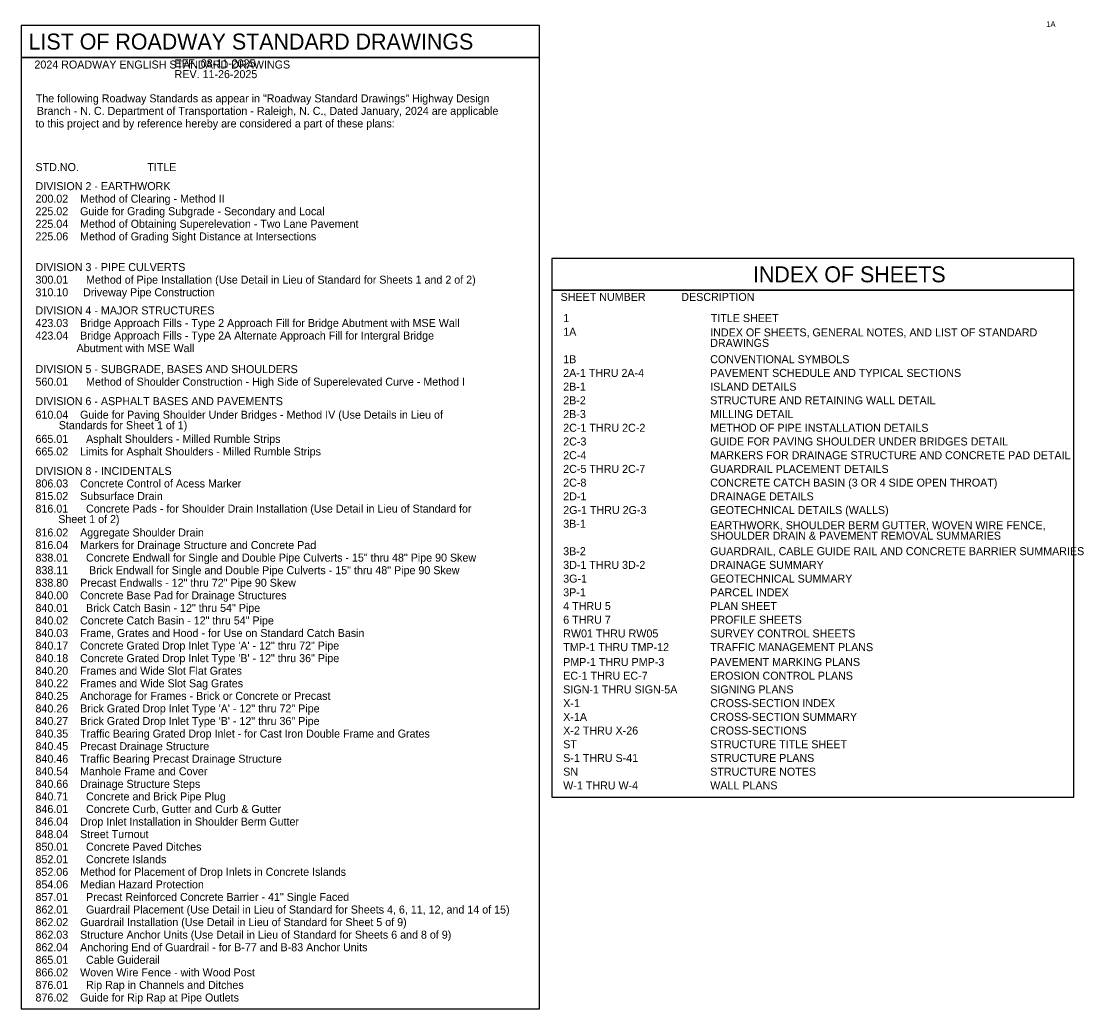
# Model space of a CAD drawing. Extents: x 4758945 to 4761296, y 1218805 to 1219686.
# Drawn here: x 4760367 to 4761296, y 1218805 to 1219669 of the extents above; entities that cross this region are included whole.
import ezdxf

# ---------------------------------------------------------------- set-up
doc = ezdxf.new("R2010")
doc.units = 0
for name, color, linetype in [('Old_Level_44', 7, 'Continuous'), ('Scratch_Level_3', 7, 'Continuous'), ('Typical Text Grade Point CELL', 7, 'Continuous')]:
    doc.layers.add(name, color=color, linetype=linetype)

msp = doc.modelspace()

# ---------------------------------------------------------------- linework, layer by layer
at = {"layer": 'Old_Level_44'}
msp.add_line((4760830.64, 1219433.79), (4761287.5, 1219433.79), dxfattribs=at)
msp.add_lwpolyline([(4760366.66, 1219637.5), (4760820.07, 1219637.5), (4760820.07, 1219665.5), (4760366.66, 1219665.5)], close=True, dxfattribs=at)
at = {"layer": 'Typical Text Grade Point CELL'}
for points in [[(4760366.66, 1218805), (4760820.07, 1218805), (4760820.07, 1219637.5), (4760366.66, 1219637.5)], [(4760830.64, 1219433.79), (4761287.5, 1219433.79), (4761287.5, 1219461.64), (4760830.64, 1219461.64)], [(4760830.64, 1218990.15), (4761287.5, 1218990.15), (4761287.5, 1219433.79), (4760830.64, 1219433.79)]]:
    msp.add_lwpolyline(points, close=True, dxfattribs=at)

# ---------------------------------------------------------------- texts
at = {"layer": 'Old_Level_44'}
for s, p in [('LIST OF ROADWAY STANDARD DRAWINGS', (4760373.07, 1219644.5)), ('INDEX OF SHEETS', (4761006.75, 1219440.79))]:
    msp.add_text(s, height=14, dxfattribs=at).set_placement(p)
at = {"layer": 'Scratch_Level_3'}
msp.add_text('1A', height=5, dxfattribs=at).set_placement((4761263.23, 1219664.27))
at = {"layer": 'Typical Text Grade Point CELL'}
for s, p in [('2024 ROADWAY ENGLISH STANDARD DRAWINGS', (4760378.18, 1219627.88)), ('                                                      EFF. 08-11-2025', (4760360.38, 1219628.9)), ('                                                      EFF. 08-11-2025', (4760360.38, 1219628.9)), ('                                                      REV. 11-26-2025', (4760360.38, 1219619.46)), ('The following Roadway Standards as appear in "Roadway Standard Drawings" Highway Design ', (4760379.35, 1219598.31)), ('Branch - N. C. Department of Transportation - Raleigh, N. C., Dated January, 2024 are applicable ', (4760380.29, 1219587.31)), ('to this project and by reference hereby are considered a part of these plans:', (4760379.12, 1219576.31)), ('STD.NO.                       TITLE', (4760379.12, 1219538.13)), ('DIVISION 2 - EARTHWORK', (4760379.12, 1219521.48)), ('200.02    Method of Clearing - Method II', (4760379.12, 1219510.48)), ('225.02    Guide for Grading Subgrade - Secondary and Local', (4760379.12, 1219499.48)), ('225.04    Method of Obtaining Superelevation - Two Lane Pavement', (4760379.12, 1219488.48)), ('225.06    Method of Grading Sight Distance at Intersections', (4760379.12, 1219477.48)), ('DIVISION 3 - PIPE CULVERTS', (4760379.12, 1219450.59)), ('300.01      Method of Pipe Installation (Use Detail in Lieu of Standard for Sheets 1 and 2 of 2)', (4760379.12, 1219439.59)), ('310.10     Driveway Pipe Construction', (4760379.12, 1219428.59)), ('SHEET NUMBER            DESCRIPTION', (4760838.46, 1219424.5)), ('DIVISION 4 - MAJOR STRUCTURES', (4760379.12, 1219412.69)), ('1 ', (4760840.74, 1219405.98)), ('TITLE SHEET', (4760969.86, 1219405.98)), ('423.03    Bridge Approach Fills - Type 2 Approach Fill for Bridge Abutment with MSE Wall', (4760379.12, 1219401.69)), ('423.04    Bridge Approach Fills - Type 2A Alternate Approach Fill for Intergral Bridge', (4760379.12, 1219390.69)), ('1A ', (4760840.74, 1219393.98)), ('INDEX OF SHEETS, GENERAL NOTES, AND LIST OF STANDARD ', (4760969.34, 1219393.44)), ('    Abutment with MSE Wall', (4760404.66, 1219379.69)), ('DRAWINGS', (4760969.34, 1219384.26)), ('1B  ', (4760840.74, 1219369.98)), ('CONVENTIONAL SYMBOLS ', (4760969.34, 1219369.98)), ('DIVISION 5 - SUBGRADE, BASES AND SHOULDERS', (4760379.12, 1219361.3)), ('560.01      Method of Shoulder Construction - High Side of Superelevated Curve - Method I', (4760379.12, 1219350.3)), ('2A-1 THRU 2A-4', (4760840.74, 1219357.98)), ('PAVEMENT SCHEDULE AND TYPICAL SECTIONS', (4760969.34, 1219357.98)), ('2B-1   ', (4760840.74, 1219345.98)), ('ISLAND DETAILS', (4760969.34, 1219345.98)), ('DIVISION 6 - ASPHALT BASES AND PAVEMENTS', (4760379.12, 1219333.27)), ('2B-2', (4760840.74, 1219333.98)), ('STRUCTURE AND RETAINING WALL DETAIL', (4760969.34, 1219333.98)), ('610.04    Guide for Paving Shoulder Under Bridges - Method IV (Use Details in Lieu of ', (4760379.12, 1219321.42)), ('2B-3', (4760840.74, 1219321.98)), ('MILLING DETAIL', (4760969.34, 1219321.98)), ('       Standards for Sheet 1 of 1)', (4760381.27, 1219312.24)), ('2C-1 THRU 2C-2  ', (4760840.74, 1219309.98)), ('METHOD OF PIPE INSTALLATION DETAILS', (4760969.34, 1219309.98)), ('665.01      Asphalt Shoulders - Milled Rumble Strips', (4760379.12, 1219300.27)), ('2C-3 ', (4760840.74, 1219297.98)), ('GUIDE FOR PAVING SHOULDER UNDER BRIDGES DETAIL', (4760969.34, 1219297.98)), ('665.02    Limits for Asphalt Shoulders - Milled Rumble Strips', (4760379.12, 1219289.27)), ('2C-4', (4760840.74, 1219285.98)), ('MARKERS FOR DRAINAGE STRUCTURE AND CONCRETE PAD DETAIL', (4760969.34, 1219285.98)), ('DIVISION 8 - INCIDENTALS', (4760379.12, 1219272.23)), ('2C-5 THRU 2C-7   ', (4760840.74, 1219273.98)), ('GUARDRAIL PLACEMENT DETAILS', (4760969.34, 1219273.98)), ('806.03    Concrete Control of Acess Marker', (4760379.12, 1219261.23)), ('2C-8 ', (4760840.74, 1219261.98)), ('CONCRETE CATCH BASIN (3 OR 4 SIDE OPEN THROAT)', (4760969.34, 1219261.98)), ('815.02    Subsurface Drain', (4760379.12, 1219250.23)), ('2D-1  ', (4760840.74, 1219249.98)), ('DRAINAGE DETAILS', (4760969.34, 1219249.98)), ('816.01      Concrete Pads - for Shoulder Drain Installation (Use Detail in Lieu of Standard for ', (4760379.12, 1219239.23)), ('       Sheet 1 of 2)', (4760380.81, 1219230.05)), ('2G-1 THRU 2G-3 ', (4760840.74, 1219237.98)), ('GEOTECHNICAL DETAILS (WALLS)', (4760969.34, 1219237.98)), ('3B-1     ', (4760840.74, 1219225.98)), ('EARTHWORK, SHOULDER BERM GUTTER, WOVEN WIRE FENCE, ', (4760969.34, 1219224.7)), ('816.02    Aggregate Shoulder Drain', (4760379.12, 1219218.34)), ('SHOULDER DRAIN & PAVEMENT REMOVAL SUMMARIES', (4760969.34, 1219215.52)), ('816.04    Markers for Drainage Structure and Concrete Pad', (4760379.12, 1219207.34)), ('3B-2     ', (4760840.74, 1219201.98)), ('GUARDRAIL, CABLE GUIDE RAIL AND CONCRETE BARRIER SUMMARIES', (4760969.34, 1219201.98)), ('838.01      Concrete Endwall for Single and Double Pipe Culverts - 15" thru 48" Pipe 90 Skew', (4760379.12, 1219196.34)), ('838.11       Brick Endwall for Single and Double Pipe Culverts - 15" thru 48" Pipe 90 Skew', (4760379.12, 1219185.34)), ('3D-1 THRU 3D-2     ', (4760840.74, 1219189.98)), ('DRAINAGE SUMMARY', (4760969.34, 1219189.98)), ('838.80    Precast Endwalls - 12" thru 72" Pipe 90 Skew', (4760379.12, 1219174.34)), ('3G-1     ', (4760840.74, 1219177.98)), ('GEOTECHNICAL SUMMARY', (4760969.34, 1219177.98)), ('3P-1     ', (4760840.74, 1219165.98)), ('PARCEL INDEX', (4760969.34, 1219165.98)), ('840.00    Concrete Base Pad for Drainage Structures', (4760379.12, 1219163.34)), ('840.01      Brick Catch Basin - 12" thru 54" Pipe', (4760379.12, 1219152.34)), ('4 THRU 5  ', (4760840.74, 1219153.98)), ('PLAN SHEET', (4760969.34, 1219153.98)), ('840.02    Concrete Catch Basin - 12" thru 54" Pipe', (4760379.12, 1219141.34)), ('6 THRU 7', (4760840.74, 1219141.98)), ('PROFILE SHEETS', (4760969.34, 1219141.98)), ('840.03    Frame, Grates and Hood - for Use on Standard Catch Basin', (4760379.12, 1219130.34)), ('RW01 THRU RW05', (4760840.74, 1219129.98)), ('SURVEY CONTROL SHEETS', (4760969.34, 1219129.98)), ('840.17    Concrete Grated Drop Inlet Type \'A\' - 12" thru 72" Pipe', (4760379.12, 1219119.34)), ('TMP-1 THRU TMP-12', (4760840.74, 1219117.98)), ('TRAFFIC MANAGEMENT PLANS', (4760969.34, 1219117.98)), ('840.18    Concrete Grated Drop Inlet Type \'B\' - 12" thru 36" Pipe', (4760379.12, 1219108.34)), ('PMP-1 THRU PMP-3', (4760840.74, 1219104.98)), ('PAVEMENT MARKING PLANS', (4760969.34, 1219104.98)), ('840.20    Frames and Wide Slot Flat Grates', (4760379.12, 1219097.34)), ('EC-1 THRU EC-7', (4760840.74, 1219092.98)), ('EROSION CONTROL PLANS', (4760969.34, 1219092.98)), ('840.22    Frames and Wide Slot Sag Grates', (4760379.12, 1219086.34)), ('SIGN-1 THRU SIGN-5A', (4760840.74, 1219080.98)), ('SIGNING PLANS', (4760969.34, 1219080.98)), ('840.25    Anchorage for Frames - Brick or Concrete or Precast', (4760379.12, 1219075.34)), ('840.26    Brick Grated Drop Inlet Type \'A\' - 12" thru 72" Pipe', (4760379.12, 1219064.34)), ('X-1', (4760840.74, 1219068.98)), ('CROSS-SECTION INDEX', (4760969.34, 1219068.98)), ('840.27    Brick Grated Drop Inlet Type \'B\' - 12" thru 36" Pipe', (4760379.12, 1219053.34)), ('X-1A ', (4760840.74, 1219056.98)), ('CROSS-SECTION SUMMARY', (4760969.34, 1219056.98)), ('X-2 THRU X-26', (4760840.74, 1219044.98)), ('CROSS-SECTIONS', (4760969.34, 1219044.98)), ('840.35    Traffic Bearing Grated Drop Inlet - for Cast Iron Double Frame and Grates', (4760379.12, 1219042.34)), ('840.45    Precast Drainage Structure', (4760379.12, 1219031.34)), ('ST', (4760840.74, 1219032.98)), ('STRUCTURE TITLE SHEET', (4760969.34, 1219032.98)), ('840.46    Traffic Bearing Precast Drainage Structure', (4760379.12, 1219020.34)), ('S-1 THRU S-41', (4760840.74, 1219020.98)), ('STRUCTURE PLANS', (4760969.34, 1219020.98)), ('840.54    Manhole Frame and Cover', (4760379.12, 1219009.34)), ('SN ', (4760840.74, 1219008.98)), ('STRUCTURE NOTES', (4760969.34, 1219008.98)), ('840.66    Drainage Structure Steps', (4760379.12, 1218998.34)), ('WALL PLANS', (4760969.34, 1218996.98)), ('W-1 THRU W-4', (4760840.74, 1218996.98)), ('840.71      Concrete and Brick Pipe Plug', (4760379.12, 1218987.34)), ('846.01      Concrete Curb, Gutter and Curb & Gutter', (4760379.12, 1218976.34)), ('846.04    Drop Inlet Installation in Shoulder Berm Gutter', (4760379.12, 1218965.34)), ('848.04    Street Turnout', (4760379.12, 1218954.34)), ('850.01      Concrete Paved Ditches', (4760379.12, 1218943.34)), ('852.01      Concrete Islands', (4760379.12, 1218932.34)), ('852.06    Method for Placement of Drop Inlets in Concrete Islands', (4760379.12, 1218921.34)), ('854.06    Median Hazard Protection', (4760379.12, 1218910.34)), ('857.01      Precast Reinforced Concrete Barrier - 41" Single Faced', (4760379.12, 1218899.34)), ('862.01      Guardrail Placement (Use Detail in Lieu of Standard for Sheets 4, 6, 11, 12, and 14 of 15)', (4760379.12, 1218888.34)), ('862.02    Guardrail Installation (Use Detail in Lieu of Standard for Sheet 5 of 9)', (4760379.12, 1218877.34)), ('862.03    Structure Anchor Units (Use Detail in Lieu of Standard for Sheets 6 and 8 of 9)', (4760379.12, 1218866.34)), ('862.04    Anchoring End of Guardrail - for B-77 and B-83 Anchor Units', (4760379.12, 1218855.34)), ('865.01      Cable Guiderail', (4760379.12, 1218844.34)), ('866.02    Woven Wire Fence - with Wood Post', (4760379.12, 1218833.34)), ('876.01      Rip Rap in Channels and Ditches', (4760379.12, 1218822.34)), ('876.02    Guide for Rip Rap at Pipe Outlets', (4760379.12, 1218811.34))]:
    msp.add_text(s, height=7, dxfattribs=at).set_placement(p)

doc.saveas('drawing.dxf')
